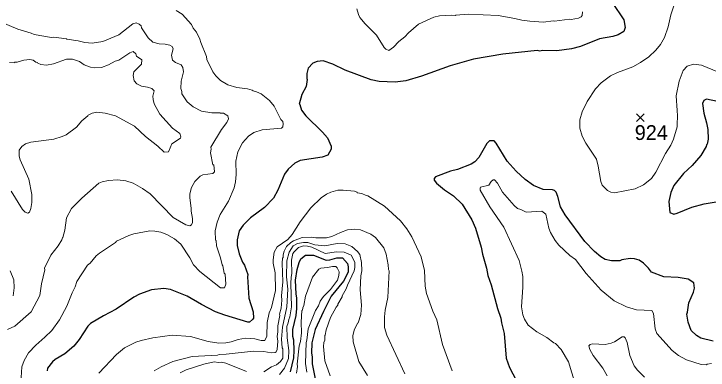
# Model space of a CAD drawing. Extents: x 265.7 to 292.1, y 7676.2 to 7704.2.
# Drawn here: x 268.132 to 271.891, y 7699.898 to 7701.825 of the extents above; entities that cross this region are included whole.
import ezdxf
from ezdxf.enums import TextEntityAlignment as Align

# ---------------------------------------------------------------- set-up
doc = ezdxf.new("R2010")
doc.units = 0
doc.header["$LTSCALE"] = 0.032
for name, color, linetype, lineweight in [('1', 7, 'Continuous', 25), ('2', 7, 'Continuous', 13), ('21', 7, 'Continuous', 25)]:
    doc.layers.add(name, color=color, linetype=linetype, lineweight=lineweight)
doc.layers.add('61', color=7, linetype='Continuous')

msp = doc.modelspace()

# ---------------------------------------------------------------- linework, layer by layer
at = {"layer": '1'}
for points in [[(271.9533, 7702.2912), (271.8736, 7702.2736), (271.8432, 7702.2712), (271.7954, 7702.2592), (271.7634, 7702.2473), (271.6836, 7702.1906), (271.6445, 7702.1818), (271.5927, 7702.193), (271.5791, 7702.1986), (271.5177, 7702.2002), (271.4841, 7702.1962), (271.4347, 7702.1643), (271.398, 7702.122), (271.3788, 7702.0909), (271.3573, 7702.0334), (271.3485, 7701.9903), (271.3533, 7701.9441), (271.3724, 7701.8866), (271.4347, 7701.7925), (271.4426, 7701.7518), (271.4347, 7701.7302), (271.4044, 7701.7126), (271.3756, 7701.7031), (271.3038, 7701.6903)], [(271.3038, 7701.6903), (271.2001, 7701.6496), (271.1522, 7701.6368), (271.0724, 7701.6257), (270.9942, 7701.6273), (270.9798, 7701.6241), (270.9655, 7701.6265)], [(270.9655, 7701.6265), (270.7787, 7701.6065), (270.6208, 7701.5794), (270.4947, 7701.5435), (270.3399, 7701.4876), (270.2537, 7701.4629), (270.1962, 7701.4565), (270.1101, 7701.4589), (270.067, 7701.4685), (269.9265, 7701.5203), (269.8587, 7701.5538), (269.8068, 7701.5706), (269.7749, 7701.5682), (269.751, 7701.5594), (269.7254, 7701.5307), (269.719, 7701.5036), (269.7174, 7701.4757), (269.7206, 7701.4709), (269.7143, 7701.4318), (269.6911, 7701.3887), (269.676, 7701.3376), (269.6799, 7701.3352), (269.6887, 7701.3049), (269.7119, 7701.273), (269.8028, 7701.1852), (269.8308, 7701.1541), (269.8499, 7701.1094), (269.8499, 7701.0934), (269.8324, 7701.0615), (269.802, 7701.0495), (269.6824, 7701.032), (269.6536, 7701.0168), (269.6169, 7700.9857), (269.597, 7700.9578), (269.5618, 7700.8716), (269.5371, 7700.8285), (269.4892, 7700.7782), (269.4126, 7700.7224), (269.3727, 7700.6825), (269.3512, 7700.6514), (269.3416, 7700.6035), (269.3408, 7700.5716), (269.3512, 7700.5269), (269.3703, 7700.4822), (269.3807, 7700.4662), (269.3983, 7700.416), (269.3967, 7700.4024), (269.4046, 7700.2867), (269.427, 7700.2141), (269.4286, 7700.1798), (269.4238, 7700.171), (269.407, 7700.1566), (269.3983, 7700.1566), (269.2738, 7700.1949), (269.2243, 7700.2133), (269.1485, 7700.2524), (269.0695, 7700.2987), (268.9794, 7700.3337), (268.9436, 7700.3393), (268.8764, 7700.333), (268.8126, 7700.309), (268.7807, 7700.2923), (268.6857, 7700.2276), (268.6163, 7700.1925), (268.5461, 7700.1502), (268.5325, 7700.1359), (268.4854, 7700.0641), (268.4567, 7700.0274), (268.4072, 7699.9859), (268.3561, 7699.9555), (268.341, 7699.9428), (268.3146, 7699.9093), (268.313, 7699.8949)], [(272.0108, 7701.336), (271.8831, 7701.3647), (271.868, 7701.3559), (271.8608, 7701.3408), (271.868, 7701.2881), (271.8831, 7701.2355), (271.8895, 7701.2004), (271.8919, 7701.1477), (271.8863, 7701.1198), (271.8815, 7701.1174), (271.8807, 7701.1086), (271.8512, 7701.0599), (271.8049, 7701.0057), (271.7578, 7700.961), (271.706, 7700.8963), (271.6892, 7700.8588), (271.6788, 7700.811), (271.6844, 7700.7511), (271.706, 7700.7423), (271.7235, 7700.7463), (271.8033, 7700.7798), (271.8704, 7700.7982), (272.0635, 7700.8309)], [(271.9182, 7700.0545), (271.8512, 7700.0712), (271.8281, 7700.0848), (271.7985, 7700.1127), (271.7826, 7700.1566), (271.7762, 7700.2013), (271.7802, 7700.2109), (271.7858, 7700.262), (271.8113, 7700.3194), (271.8169, 7700.3418), (271.8145, 7700.3697), (271.7834, 7700.3904), (271.7283, 7700.3984), (271.6517, 7700.4024), (271.5839, 7700.4287), (271.5679, 7700.4503), (271.5408, 7700.4774), (271.5177, 7700.4926), (271.4921, 7700.4997), (271.4682, 7700.5013), (271.4235, 7700.4942), (271.4123, 7700.4894), (271.3676, 7700.4886), (271.3341, 7700.4973), (271.3094, 7700.5101), (271.2759, 7700.5396), (271.2232, 7700.5947), (271.1163, 7700.7375), (271.0915, 7700.7822), (271.078, 7700.8381), (271.0684, 7700.8604), (271.0596, 7700.8692), (271.0485, 7700.874), (270.9974, 7700.8748), (270.9463, 7700.8963), (270.9008, 7700.9298), (270.8514, 7700.9737), (270.8027, 7701.0288), (270.7436, 7701.1254), (270.7325, 7701.1389), (270.7069, 7701.1381), (270.6926, 7701.1245), (270.6495, 7701.0487), (270.6271, 7701.024), (270.608, 7701.012), (270.5346, 7700.9825), (270.4963, 7700.9745), (270.4141, 7700.9442), (270.4077, 7700.9354), (270.4077, 7700.9251), (270.4205, 7700.9099), (270.4643, 7700.8732), (270.513, 7700.8405), (270.5593, 7700.795), (270.6112, 7700.7104), (270.6319, 7700.6657), (270.6622, 7700.5636), (270.6686, 7700.5253), (270.691, 7700.4487), (270.6989, 7700.4104), (270.7165, 7700.3593), (270.75, 7700.2316), (270.7692, 7700.179), (270.7724, 7700.1534), (270.7867, 7700.096), (270.7979, 7699.9619), (270.8154, 7699.9125), (270.8721, 7699.8055)], [(269.6297, 7699.8885), (269.6472, 7699.9651), (269.6496, 7700.0034), (269.6472, 7700.0609), (269.6424, 7700.08), (269.6424, 7700.1183), (269.66, 7700.1933), (269.6648, 7700.2316), (269.6648, 7700.2891), (269.66, 7700.3082), (269.6576, 7700.3848), (269.6664, 7700.4423), (269.6768, 7700.4806), (269.6855, 7700.4998), (269.7103, 7700.5205), (269.755, 7700.5197), (269.8228, 7700.4934), (269.8419, 7700.4949), (269.8802, 7700.5053), (269.9106, 7700.5053), (269.9393, 7700.475), (269.9425, 7700.4567), (269.9417, 7700.4271), (269.9161, 7700.3801), (269.8507, 7700.2979), (269.8084, 7700.2157), (269.7637, 7700.1175), (269.7446, 7700.0465), (269.743, 7699.9891), (269.747, 7699.9699), (269.7462, 7699.9316), (269.7741, 7699.7975)]]:
    msp.add_lwpolyline(points, dxfattribs=at)
at = {"layer": '2'}
for points in [[(271.9773, 7701.498), (271.8544, 7701.5483), (271.8113, 7701.5531), (271.7778, 7701.5427), (271.7562, 7701.5187), (271.7339, 7701.4621), (271.7187, 7701.3823), (271.7243, 7701.3025), (271.7227, 7701.2905), (271.7251, 7701.2857), (271.7235, 7701.2147), (271.7044, 7701.1477), (271.6884, 7701.1142), (271.6597, 7701.0695), (271.6078, 7700.969), (271.5847, 7700.9354), (271.5416, 7700.8995), (271.4969, 7700.8788), (271.3836, 7700.8572), (271.3645, 7700.8604), (271.3461, 7700.8692), (271.3182, 7700.8979), (271.3094, 7700.9179), (271.2966, 7701.0009), (271.2862, 7701.0392), (271.2288, 7701.1254), (271.2096, 7701.1637), (271.1961, 7701.2067), (271.1961, 7701.2514), (271.2096, 7701.2961), (271.236, 7701.352), (271.2815, 7701.419), (271.3118, 7701.4517), (271.3629, 7701.4892), (271.4012, 7701.5084), (271.4826, 7701.5395), (271.5256, 7701.5618), (271.5703, 7701.5922), (271.6078, 7701.6289), (271.6326, 7701.66), (271.6549, 7701.6983), (271.6749, 7701.7557), (271.69, 7701.8196), (271.7259, 7701.9313)], [(269.9888, 7701.8531), (269.9975, 7701.8212), (270.0055, 7701.8052), (270.0342, 7701.7717), (270.0957, 7701.7095), (270.1364, 7701.6432), (270.1452, 7701.6337), (270.1619, 7701.6273), (270.1883, 7701.6456), (270.217, 7701.6751), (270.2481, 7701.7007), (270.268, 7701.723), (270.3223, 7701.7693), (270.4053, 7701.8076), (270.4372, 7701.814), (270.5011, 7701.818), (270.5234, 7701.8164), (270.5242, 7701.8188), (270.592, 7701.8236), (270.7548, 7701.8156), (270.8442, 7701.8004), (270.8825, 7701.7909), (270.9256, 7701.7853), (271.0006, 7701.7813), (271.0517, 7701.7869), (271.0596, 7701.7853), (271.141, 7701.7964), (271.149, 7701.7948), (271.1889, 7701.8012), (271.2041, 7701.8084), (271.2096, 7701.8156), (271.2104, 7701.8355)], [(268.2109, 7699.9922), (268.2508, 7700.0337), (268.3003, 7700.076), (268.337, 7700.1127), (268.3785, 7700.1702), (268.4192, 7700.2444), (268.4479, 7700.3162), (268.4639, 7700.3481), (268.4734, 7700.3769), (268.5301, 7700.4662), (268.5452, 7700.4774), (268.578, 7700.5157), (268.5955, 7700.5309), (268.6817, 7700.5891), (268.6873, 7700.5955), (268.7535, 7700.6266), (268.7822, 7700.6362), (268.8684, 7700.6514), (268.8956, 7700.6506), (268.9275, 7700.6442), (268.9594, 7700.6322), (269.0025, 7700.6083), (269.0352, 7700.5803), (269.0847, 7700.5061), (269.1046, 7700.4678), (269.1389, 7700.4311), (269.2515, 7700.3425), (269.273, 7700.3425), (269.2802, 7700.3625), (269.2754, 7700.4176), (269.2706, 7700.4231), (269.2642, 7700.4622), (269.2594, 7700.4678), (269.2514, 7700.5061), (269.2291, 7700.57), (269.2275, 7700.5987), (269.2243, 7700.6011), (269.2227, 7700.6514), (269.2331, 7700.6992), (269.2483, 7700.7391), (269.2945, 7700.8126), (269.3249, 7700.8844), (269.332, 7700.9163), (269.3352, 7700.9562), (269.3336, 7701.0288), (269.3448, 7701.0791), (269.3695, 7701.127), (269.4023, 7701.1636), (269.4318, 7701.1844), (269.4765, 7701.1972), (269.5802, 7701.2075), (269.5882, 7701.2139), (269.5898, 7701.2307), (269.5874, 7701.2427), (269.5778, 7701.2546), (269.5419, 7701.3264), (269.5156, 7701.356), (269.4717, 7701.3919), (269.4462, 7701.4038), (269.4278, 7701.4086), (269.423, 7701.4134), (269.3967, 7701.4198), (269.3392, 7701.4262), (269.2913, 7701.4413), (269.2515, 7701.4645), (269.2259, 7701.4892), (269.2084, 7701.5124), (269.1764, 7701.5786), (269.174, 7701.5946), (269.1437, 7701.6696), (269.1389, 7701.6887), (269.1206, 7701.727), (269.103, 7701.7478), (269.0942, 7701.7669), (269.0432, 7701.8244), (269.0113, 7701.8435)], [(268.0098, 7701.8028), (268.1535, 7701.7422), (268.2253, 7701.7214), (268.2412, 7701.7134), (268.3354, 7701.6975), (268.349, 7701.6991), (268.4176, 7701.6911), (268.4184, 7701.6879), (268.4806, 7701.6799), (268.5157, 7701.6704), (268.5556, 7701.6672), (268.6131, 7701.6767), (268.6993, 7701.7111), (268.7767, 7701.7709), (268.7942, 7701.7765), (268.8094, 7701.7701), (268.8205, 7701.7605)], [(268.8205, 7701.7605), (268.8221, 7701.7502), (268.8596, 7701.6951), (268.8844, 7701.672), (268.9179, 7701.6624), (268.9514, 7701.6608), (268.977, 7701.656)], [(268.977, 7701.656), (268.9897, 7701.648), (268.9945, 7701.6361), (268.9849, 7701.6017), (268.9905, 7701.5746), (269.0073, 7701.5626), (269.0384, 7701.5491), (269.0472, 7701.5355), (269.0496, 7701.5116), (269.0384, 7701.4621), (269.036, 7701.4222), (269.0408, 7701.4062), (269.0408, 7701.3935), (269.0695, 7701.3488), (269.103, 7701.3224), (269.1477, 7701.2985), (269.2036, 7701.2905), (269.2483, 7701.2905), (269.2491, 7701.2873), (269.2674, 7701.2873), (269.2913, 7701.273), (269.2937, 7701.2578), (269.285, 7701.2371), (269.257, 7701.1996), (269.1988, 7701.1046), (269.2004, 7701.0926), (269.1972, 7701.0727), (269.2099, 7701.0088), (269.2139, 7701.0081), (269.2179, 7700.9713), (269.2092, 7700.961), (269.1557, 7700.9538), (269.1397, 7700.9466), (269.111, 7700.9179), (269.0934, 7700.886), (269.0855, 7700.8524), (269.0839, 7700.8301), (269.0927, 7700.7743), (269.0919, 7700.7583), (269.0998, 7700.7184), (269.0982, 7700.6968), (269.0934, 7700.6833), (269.0839, 7700.6793), (269.0623, 7700.6833), (268.9937, 7700.724), (268.8692, 7700.8517), (268.8277, 7700.8804), (268.7775, 7700.9091), (268.7376, 7700.9219), (268.6929, 7700.9275), (268.645, 7700.9243), (268.6091, 7700.9171), (268.5923, 7700.9099), (268.499, 7700.8285), (268.4431, 7700.7727), (268.416, 7700.7216), (268.4072, 7700.6546), (268.3976, 7700.6155), (268.3944, 7700.6139), (268.3912, 7700.6027), (268.3721, 7700.57), (268.3322, 7700.5205), (268.2979, 7700.4487), (268.2987, 7700.4407), (268.2819, 7700.3657), (268.2723, 7700.3019), (268.2253, 7700.2141), (268.1375, 7700.1359), (268.0976, 7700.1183)], [(268.108, 7701.5626), (268.1343, 7701.561), (268.1359, 7701.5634), (268.1503, 7701.5634), (268.1854, 7701.5754), (268.2189, 7701.5778), (268.2372, 7701.5746), (268.25, 7701.5642), (268.2604, 7701.5618), (268.2612, 7701.5586), (268.2771, 7701.5515), (268.3083, 7701.5483), (268.3465, 7701.5546), (268.4168, 7701.581), (268.4487, 7701.581), (268.487, 7701.5674), (268.5133, 7701.5491), (268.5476, 7701.5363), (268.5668, 7701.5331), (268.6067, 7701.5347), (268.645, 7701.5491), (268.6801, 7701.5698), (268.6993, 7701.5754), (268.7591, 7701.6153), (268.7775, 7701.6217), (268.7918, 7701.6097), (268.7958, 7701.5961), (268.8245, 7701.5762), (268.8221, 7701.5539), (268.7814, 7701.5124), (268.7783, 7701.4924), (268.783, 7701.4637), (268.7982, 7701.4477), (268.8221, 7701.4342), (268.8557, 7701.4294), (268.878, 7701.4222)], [(268.878, 7701.4222), (268.8916, 7701.4086), (268.8844, 7701.3807), (268.886, 7701.3616), (268.8924, 7701.3392), (268.9227, 7701.2834), (268.9905, 7701.2075)], [(268.9905, 7701.2075), (269.0296, 7701.1788), (269.0368, 7701.1605), (269.0336, 7701.1525), (268.9873, 7701.1222), (268.969, 7701.0783), (268.945, 7701.0767), (268.9107, 7701.1102), (268.8453, 7701.1613), (268.7846, 7701.2171), (268.6817, 7701.273), (268.6258, 7701.2881), (268.5812, 7701.2929), (268.5564, 7701.2889), (268.5333, 7701.2778), (268.5317, 7701.273), (268.4998, 7701.2458), (268.4718, 7701.2123), (268.4152, 7701.1716), (268.3928, 7701.1613), (268.3482, 7701.1477), (268.2237, 7701.1309), (268.1949, 7701.1214), (268.1742, 7701.1086), (268.1598, 7701.0878), (268.1614, 7701.0551), (268.1662, 7701.036), (268.2125, 7700.9307), (268.2285, 7700.8477), (268.2293, 7700.8046), (268.2237, 7700.7727), (268.2165, 7700.7527), (268.2069, 7700.7471), (268.1933, 7700.7527), (268.1782, 7700.7663), (268.1175, 7700.8668)], [(270.8809, 7700.2412), (270.8881, 7700.3465), (270.8873, 7700.404), (270.8833, 7700.4327), (270.8681, 7700.4902), (270.7851, 7700.6705), (270.7085, 7700.7822), (270.6559, 7700.8716), (270.6559, 7700.8828), (270.659, 7700.8884), (270.7029, 7700.8987), (270.7165, 7700.9179), (270.7269, 7700.9267), (270.7341, 7700.9275), (270.75, 7700.9091), (270.7771, 7700.8604), (270.8402, 7700.7886), (270.8585, 7700.7719), (270.8777, 7700.7671), (270.9064, 7700.7527), (270.991, 7700.7583), (271.0126, 7700.7423), (271.0293, 7700.6657), (271.0373, 7700.6434), (271.0628, 7700.5987), (271.0836, 7700.5748), (271.1418, 7700.5189), (271.1729, 7700.4973), (271.2312, 7700.42), (271.3118, 7700.3298), (271.382, 7700.2731), (271.449, 7700.2412), (271.5033, 7700.2245), (271.5855, 7700.2197), (271.5959, 7700.2037), (271.6046, 7700.1215), (271.6142, 7700.096), (271.6964, 7700.0034), (271.7299, 7699.9779), (271.7746, 7699.9531), (271.8528, 7699.9292), (271.8815, 7699.9268), (271.8863, 7699.93), (271.9087, 7699.9332)], [(268.5923, 7699.8813), (268.6881, 7699.9827), (268.7312, 7700.0194), (268.7918, 7700.0489), (268.8206, 7700.0585), (268.8844, 7700.0728), (268.9881, 7700.0864), (269.0887, 7700.0792), (269.1844, 7700.0537), (269.2419, 7700.0433), (269.2802, 7700.0449), (269.3089, 7700.0505), (269.3472, 7700.0641), (269.3855, 7700.0704), (269.4366, 7700.0665), (269.4701, 7700.0585), (269.49, 7700.0585), (269.502, 7700.0816), (269.5028, 7700.1558), (269.5148, 7700.2077), (269.5267, 7700.2364), (269.5483, 7700.329), (269.5467, 7700.4239), (269.5355, 7700.4758), (269.5355, 7700.495), (269.5419, 7700.5365), (269.5571, 7700.5644), (269.6153, 7700.6051), (269.6393, 7700.6322), (269.6823, 7700.7008), (269.7406, 7700.7766), (269.7965, 7700.8293), (269.8252, 7700.8501), (269.8483, 7700.8612), (269.8866, 7700.8716), (269.9154, 7700.8724), (269.976, 7700.866), (269.9904, 7700.8612), (269.9904, 7700.858), (270.0159, 7700.8532), (270.0398, 7700.8421), (270.0478, 7700.8413), (270.1388, 7700.7854), (270.2258, 7700.7064), (270.2601, 7700.6617), (270.2872, 7700.6194), (270.3375, 7700.5117), (270.3558, 7700.4375), (270.359, 7700.3513), (270.367, 7700.313), (270.3997, 7700.2173), (270.4213, 7700.1694), (270.4524, 7700.0369), (270.505, 7699.8933)], [(269.9393, 7700.6569), (269.901, 7700.6434), (269.8531, 7700.6202), (269.8244, 7700.6139), (269.7669, 7700.6139), (269.7414, 7700.6178), (269.6935, 7700.6155), (269.6456, 7700.5979), (269.6313, 7700.5891), (269.6089, 7700.5676), (269.5954, 7700.5412), (269.5898, 7700.5221), (269.5898, 7700.5069), (269.5866, 7700.5029), (269.5842, 7700.4774), (269.5882, 7700.3753), (269.5818, 7700.3003), (269.5834, 7700.2763), (269.5786, 7700.2332), (269.5706, 7700.2013), (269.5722, 7700.1933), (269.5603, 7700.1375), (269.5611, 7700.1056), (269.5579, 7700.08), (269.5611, 7700.0545), (269.5579, 7700.0098), (269.5523, 7699.9962), (269.5467, 7699.993), (269.5244, 7699.9922), (269.4845, 7699.9994), (269.4286, 7700.0002), (269.2818, 7699.9835), (269.2435, 7699.9819), (269.2339, 7699.9787), (269.0966, 7699.9723), (268.9929, 7699.9452), (268.9291, 7699.9156), (268.8908, 7699.8933)], [(270.1484, 7700.5253), (270.1356, 7700.5604), (270.0909, 7700.6155), (270.0654, 7700.633), (270.0095, 7700.6569), (269.9776, 7700.6609), (269.9393, 7700.6569)], [(269.4861, 7699.8885), (269.5275, 7699.9156), (269.5531, 7699.9268), (269.5762, 7699.9444), (269.5874, 7699.9619), (269.5882, 7700.0138), (269.585, 7700.0178), (269.581, 7700.0657), (269.5858, 7700.1295), (269.6105, 7700.2412), (269.6153, 7700.3362), (269.6073, 7700.4024), (269.6097, 7700.4886), (269.6217, 7700.5365), (269.6448, 7700.5708), (269.668, 7700.5835), (269.6999, 7700.5891), (269.7238, 7700.5883), (269.7621, 7700.5756), (269.8164, 7700.57), (269.8818, 7700.5827), (269.9249, 7700.5819), (269.9616, 7700.5668), (269.992, 7700.5397), (270.0047, 7700.5229), (270.0143, 7700.4806), (270.0159, 7700.4343), (270.0111, 7700.4072), (270.0071, 7700.3322), (270.0151, 7700.2492), (270.0111, 7700.1997), (269.9967, 7700.1542), (269.9936, 7700.1534), (269.9768, 7700.1199), (269.968, 7700.0848), (269.9688, 7700.0513), (269.9991, 7699.9444), (270.0462, 7699.8694)], [(269.9201, 7700.5365), (269.8786, 7700.538), (269.818, 7700.5285), (269.7446, 7700.5628), (269.7222, 7700.5692), (269.6999, 7700.57), (269.6736, 7700.562), (269.6496, 7700.5388), (269.6432, 7700.5285), (269.6345, 7700.4934), (269.6377, 7700.4216), (269.6329, 7700.4008), (269.6313, 7700.3673), (269.6353, 7700.2412), (269.6265, 7700.1862), (269.6201, 7700.1726), (269.6177, 7700.1534), (269.6105, 7700.1343), (269.6121, 7700.072), (269.6209, 7700.005), (269.6193, 7699.9603), (269.597, 7699.9077), (269.5698, 7699.8749)], [(269.9313, 7700.337), (269.9377, 7700.3577), (269.9752, 7700.4343), (269.9784, 7700.4535), (269.9776, 7700.4822), (269.9576, 7700.5205), (269.9201, 7700.5365)], [(270.2489, 7699.8781), (270.1515, 7700.088), (270.1396, 7700.1279), (270.138, 7700.1854), (270.142, 7700.2221), (270.1563, 7700.2907), (270.1643, 7700.4359), (270.1611, 7700.4415), (270.1595, 7700.4678), (270.1484, 7700.5253)], [(269.6624, 7699.8813), (269.668, 7699.9172), (269.6664, 7699.93), (269.676, 7700.029), (269.6839, 7700.0529), (269.6887, 7700.0992), (269.6871, 7700.1582), (269.6919, 7700.2197), (269.6951, 7700.2221), (269.6959, 7700.2348), (269.7015, 7700.2476), (269.7111, 7700.2987), (269.7494, 7700.4008), (269.7829, 7700.4447), (269.7933, 7700.4495), (269.8308, 7700.4527), (269.8563, 7700.4591), (269.8747, 7700.4583), (269.8818, 7700.4519), (269.8938, 7700.4295), (269.8922, 7700.4104), (269.8834, 7700.3848), (269.8459, 7700.3338), (269.8092, 7700.2971), (269.7909, 7700.2715), (269.7805, 7700.246), (269.7653, 7700.2205), (269.7254, 7700.1215), (269.719, 7700.0609), (269.7151, 7700.0481), (269.7103, 7699.9332), (269.7175, 7699.8877)], [(268.1279, 7700.3003), (268.1343, 7700.3434), (268.1319, 7700.3864), (268.112, 7700.4359)], [(269.8451, 7699.8662), (269.8148, 7699.9476), (269.8076, 7700.0258), (269.81, 7700.0481), (269.8148, 7700.0593), (269.8148, 7700.0856), (269.818, 7700.0872), (269.822, 7700.1151), (269.8467, 7700.1822), (269.877, 7700.238), (269.8866, 7700.2492), (269.8866, 7700.2548), (269.9098, 7700.2939), (269.909, 7700.2995), (269.9313, 7700.337)], [(271.0564, 7700.0449), (271.0181, 7700.0744), (270.9639, 7700.1056), (270.9168, 7700.1407), (270.896, 7700.1742), (270.8881, 7700.1965), (270.8809, 7700.2412)], [(271.1713, 7699.8247), (271.1354, 7699.9428), (271.0947, 7700.0098), (271.0652, 7700.0425), (271.0564, 7700.0449)], [(271.3453, 7699.8678), (271.3206, 7699.9077), (271.2679, 7699.9779), (271.2503, 7700.0098), (271.2448, 7700.029), (271.2519, 7700.0369), (271.2655, 7700.0409), (271.3333, 7700.0361), (271.366, 7700.0433), (271.3836, 7700.0513), (271.4251, 7700.0784), (271.4363, 7700.0776), (271.4427, 7700.0728), (271.453, 7700.0481), (271.4674, 7699.9763), (271.4905, 7699.9204), (271.5081, 7699.8981), (271.5472, 7699.8598)], [(268.2428, 7699.7696), (268.2005, 7699.7983), (268.1806, 7699.8215), (268.171, 7699.8582), (268.175, 7699.9164), (268.187, 7699.9508), (268.2109, 7699.9922)], [(269.0328, 7699.8829), (269.0647, 7699.8997), (269.1605, 7699.9308), (269.2163, 7699.9428), (269.2403, 7699.9388), (269.2554, 7699.9404), (269.2794, 7699.9356), (269.3919, 7699.8901)]]:
    msp.add_lwpolyline(points, dxfattribs=at)
at = {"layer": '21'}
for p, q in [((271.5042, 7701.2847), (271.5454, 7701.2435)), ((271.5454, 7701.2847), (271.5042, 7701.2435))]:
    msp.add_line(p, q, dxfattribs=at)

# ---------------------------------------------------------------- texts
at = {"layer": '61'}
msp.add_text('924', height=0.08, dxfattribs=at).set_placement((271.5833, 7701.1431), align=Align.CENTER)

doc.saveas('drawing.dxf')
